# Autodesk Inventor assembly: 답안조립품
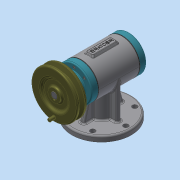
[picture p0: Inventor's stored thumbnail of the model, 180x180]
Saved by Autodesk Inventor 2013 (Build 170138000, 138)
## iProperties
Created: 2019-11
Part Number: 답안조립품
Document SubType Name: Assembly
Designer: Administrator
Author: Administrator
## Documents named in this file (18)
- C:\Users\Administrator\Desktop\391104V1007\답안조립품.iam
- C:\Users\Administrator\Desktop\391104V1007\본체.ipt
- C:\Users\Administrator\Desktop\391104V1007\본체커버.ipt
- C:\Users\Administrator\Desktop\391104V1007\개스킷.ipt
- C:\Users\Administrator\Desktop\391104V1007\뒤커버.ipt
- C:\Users\Administrator\Desktop\391104V1007\베어링 6202.ipt
- C:\Users\Administrator\Desktop\391104V1007\볼트 M3x0.5x8.ipt
- C:\Users\Administrator\Desktop\391104V1007\앞커버.ipt
- C:\Users\Administrator\Desktop\391104V1007\베어링 6201.ipt
- C:\Users\Administrator\Desktop\391104V1007\오일 실 12 22 7.ipt
- 오일 실 12 22 7.ipt
- C:\Users\Administrator\Desktop\391104V1007\편심축.ipt
- C:\Users\Administrator\Desktop\391104V1007\키 4x4x18.ipt
- 키 4x4x18.ipt
- C:\Users\Administrator\Desktop\391104V1007\V-벨트풀리.ipt
- C:\Users\Administrator\Desktop\391104V1007\멈춤나사 M3x8.ipt
- C:\Users\Administrator\Desktop\391104V1007\슬라이드.ipt
- C:\Users\Administrator\Desktop\391104V1007\가변스프링.ipt
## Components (4 placed, 3 different names)
1. 개스킷:1
2. 개스킷:2
3. V-벨트풀리:1 — 플러쉬:2
4. 가변스프링:1
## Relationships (1: Flush 1)
- 플러쉬:2 [Flush]: V-벨트풀리:1
